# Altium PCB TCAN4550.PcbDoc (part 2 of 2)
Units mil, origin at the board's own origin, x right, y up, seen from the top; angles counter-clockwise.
Board outline 2000 x 1600 mil, 2 copper layers (Top Layer, Bottom Layer), stack 62 mil thick; 83 components, 51 nets, 217 pads, 26 vias.
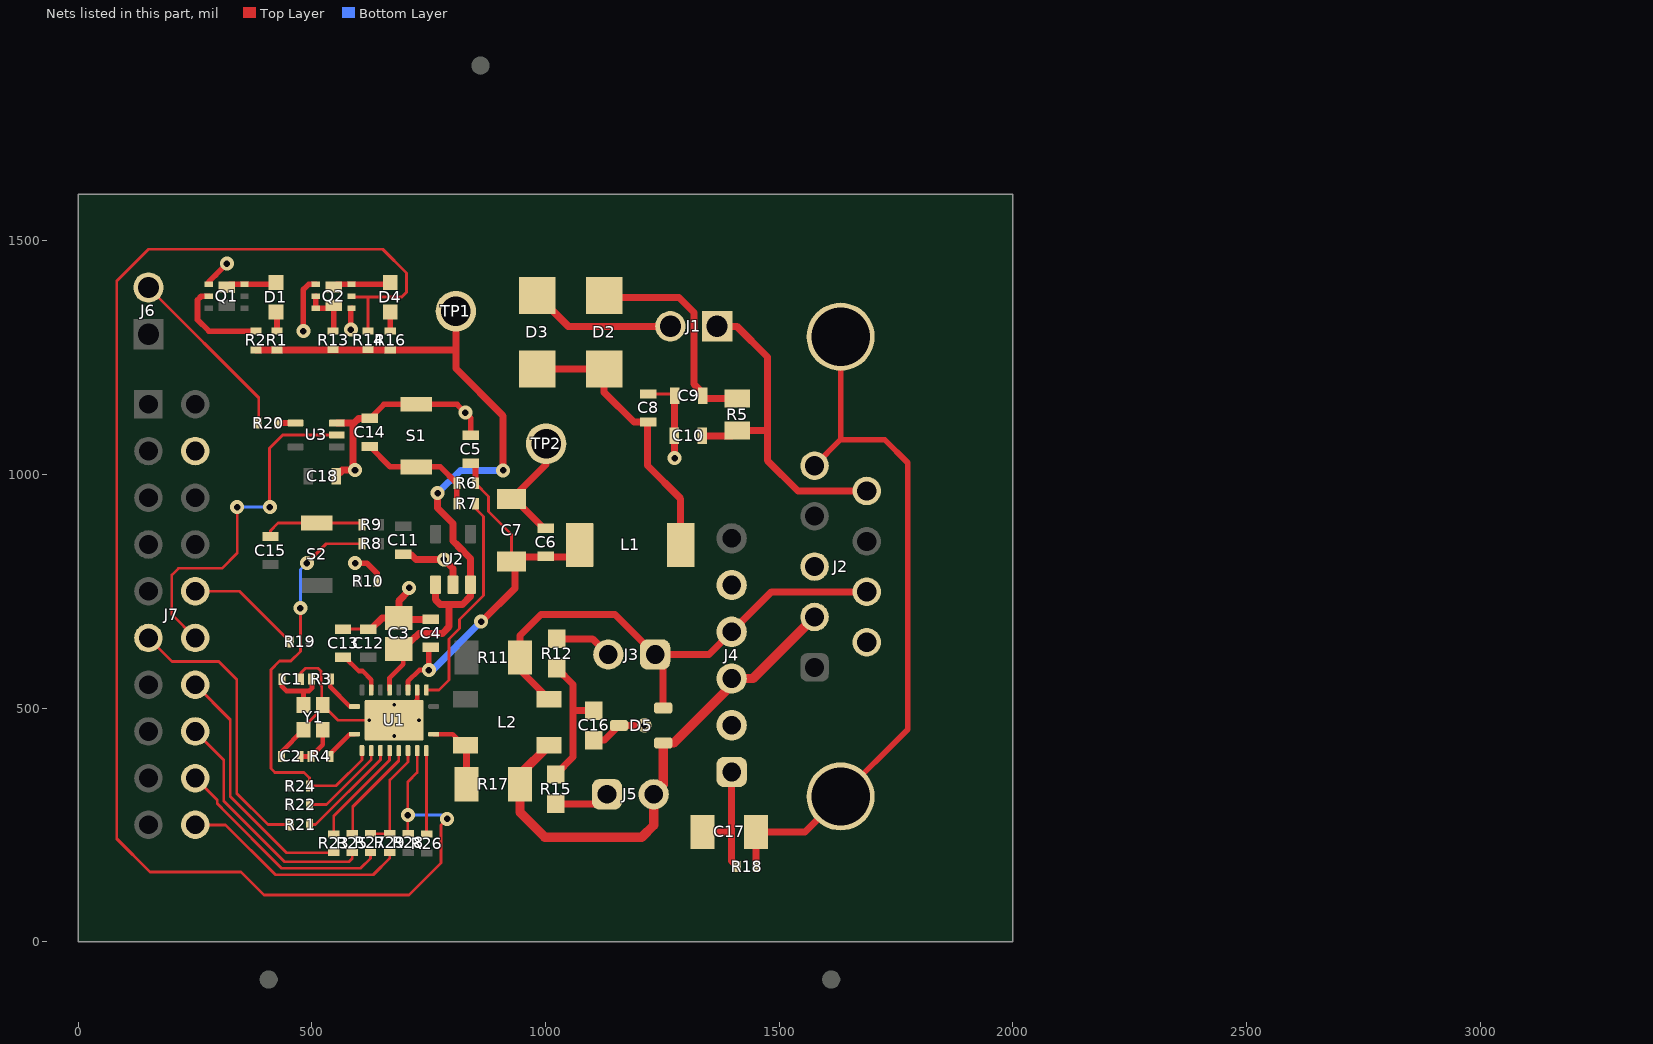
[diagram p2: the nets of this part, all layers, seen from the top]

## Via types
v1: diameter 30, hole 14, Top Layer to Bottom Layer, 22 vias
v2: diameter 19.68, hole 7.87, Top Layer to Bottom Layer, 4 vias

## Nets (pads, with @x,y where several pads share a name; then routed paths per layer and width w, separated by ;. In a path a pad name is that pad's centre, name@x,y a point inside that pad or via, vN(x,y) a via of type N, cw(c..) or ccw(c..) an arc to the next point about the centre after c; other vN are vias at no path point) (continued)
CANH_BUS: D5.2 J2.7 J3.1 J4.4 L2.4 R11.2 | length 1132.2
  Top Layer w15: L2.4@1007.53,519.04 945.05,581.53 R11.2@945.05,607.75 945.05,654.93 990.44,700.33 1148.53,700.33 J3.1@1234.31,614.55 J3.1@1242.89,614.55 ; D5.2@1251.66,500 1251.66,605.77 J3.1@1242.89,614.55 ; J2.7@1687.35,748.81 1483.78,748.81 J4.4@1398.15,663.19 1349.51,614.55 J3.1@1242.89,614.55
CANL: L2.2 R17.1 U1.10 | length 162.4
  Top Layer w10: U1.10@760.49,444.24 800.8,444.24 811.82,433.22 815.8,433.22 L2.2@828.4,420.62
  Top Layer w15: L2.2@828.4,420.62 830.87,418.14 R17.1@830.87,336.88
CANL_BUS: D5.1 J2.2 J4.3 J5.2 L2.3 R17.2 | length 1116.9
  Top Layer w20: L2.3@1007.53,420.62 945.05,358.13 R17.2@945.05,336.88 945.05,276.73 998,223.78 1206.04,223.78 1231.27,249.01 J5.2@1231.27,315.3 1251.66,335.69 D5.1@1251.66,425.2 1274.27,425.2 1398.15,549.08 J4.3@1398.15,563.19 1443.85,563.19 J2.2@1575.54,694.88
CRYSTAL1: C1.1 R3.2 Y1.1 | length 136.7
  Top Layer w10: C1.1@435.89,561.49 435.89,545.46 444.74,536.61 480,536.61 481.66,534.95 ; Y1.1@481.66,506.58 481.66,534.95 ; R3.2@499.38,561.86 500,561.24 500,542.28 494.34,536.61 481.66,536.61 481.66,534.95
CRYSTAL3: C2.1 R4.2 Y1.3 | length 91.2
  Top Layer w10: C2.1@474.24,396.43 R4.2@498.14,396.43 523,421.29 Y1.3@523,453.43
DB9_VBAT: C10.1 J1.1 J2.9 R5.2 | length 740.6
  Top Layer w15: C10.1@1335.54,1082.57 1398.61,1082.57 R5.2@1410.15,1094.11 1475,1094.11 ; J1.1@1367,1317 1409.08,1317 1475,1251.08 1475,1094.11 ; J2.9@1687.35,964.56 1539.7,964.56 1474.93,1029.34 1475,1029.41 1475,1094.11
FLTR: C13.1 U1.18 | length 102.3
  Top Layer w10: C13.1@566.37,608.9 570.49,608.9 600.1,579.3 608.13,579.3 626.63,560.8 U1.18@626.63,538.73
GND: C1.2 C2.2 C3.2 C4.2 C5.2 C6.2 C7.2 C8.2 C9.2 C10.2 C11.2 C12.2 C13.2 C14.2 C16.1 C17.2 C18.2 D3.2 D5.3 J1.2 J2.3 J2.6 J4.1 J4.2 J4.5 J7.4 Q1.4 Q2.1 Q2.4 R10.1 R18.1 S1.1 TP2.1 U1.13 U1.21 U2.2 U3.3 Y1.2 Y1.4 | length 2909.4
  Top Layer w6: C1.2@475.89,561.49 475.89,575.05 485.95,585.11 513.16,585.11 519.38,578.89 519.38,548.08 521,546.45 521,508.58 Y1.4@523,506.58 ; Y1.2@481.66,453.43 481.66,458.97 523,500.31 Y1.4@523,506.58 ; C13.2@572.39,668.9 C12.2@620.73,668.9 626.16,668.9 C12.2@626.63,669.37 ; U1.21@675.85,473.77 v2(622.7,473.77) 555.82,473.77 Y1.4@523,506.58 ; C8.2@1220,1172.16 1270.71,1172.16 1275.54,1167.33 C9.2@1276.31,1168.1
  Top Layer w10: C2.2@434.24,396.43 434.24,400.95 434.95,401.66 434.95,406.73 Y1.2@481.66,453.43 ; U1.21@675.85,473.77 680.5,473.77 725.06,518.32 U1.13@725.06,538.73
  Top Layer w12: Q1.4@278.77,1406.85 278.77,1411.72 293.69,1426.65 ; 293.67,1426.67 v1(318,1451) ; v1@318,1446.08 v1(318,1451) ; v1@318,1456.72 v1(318,1451) ; v1(481.66,1306.7) 481.66,1395.66 492.85,1406.85 Q2.4@508,1406.85 ; v1(583.02,1310) 583.02,1353.92 Q2.1@584.77,1355.67 ; v1(592.08,810) 617.44,810 639,788.44 R10.1@639,771.44 ; C14.2@623.78,1119.86 653.86,1149.94 S1.1@722.89,1149.94 810.46,1149.94 v1(828.4,1132) 840,1120.4 C5.2@840,1084
  Top Layer w15: C18.2@551.66,996 564.66,1009 v1(592,1009) 588,1013 588,1108.05 589.95,1110 ; U3.3@553.33,1110 589.95,1110 ; C14.2@623.78,1119.86 623.64,1120 599.95,1120 589.95,1110 ; C12.2@626.63,669.37 650.26,693 C3.2@685.69,693 687.05,694.36 C3.2@695.5,694.36 ; C11.2@695.33,829 711.33,829 722.33,818 v1(782.14,818) 801.82,798.31 U2.2@801.82,763.87 ; v1@707.93,751.21 685.69,728.97 685.69,704.18 C3.2@695.5,694.36 ; C4.2@754.28,689.27 700.6,689.27 C3.2@695.5,694.36 ; D3.2@982.21,1383.15 1048.36,1317 J1.2@1267,1317 ; C6.2@997.48,883.42 933.54,947.36 C7.2@927,947.36 1001,1021.36 TP2.1@1001,1065.75 ; C16.1@1102.8,431.25 1125.82,431.25 D5.3@1157.17,462.6 1204.42,462.6 1205.01,463.19 v1(1211.31,463.19) ; C9.2@1275.54,1167.33 C10.2@1275.54,1082.57 1275.54,1035.32 v1(1275.86,1035) ; C17.2@1336.07,234.83 1398.15,234.83 ; J4.1@1398.15,363.19 1398.15,234.83 ; R18.1@1410.51,160.74 1398.15,173.1 1398.15,234.83
  other v1: 707.93,757.29
  other v2: 675.85,440.3 729,473.77 675.85,507.23
GPIO1: R22.1 U1.3 | length 191.5
  Top Layer w6: R22.1@494.34,293.7 531.14,293.7 626.63,389.19 U1.3@626.63,408.81
GPIO_RST: J7.10 R19.1 | length 248.5
  Top Layer w6: J7.10@250,750 345.13,750 R19.1@453.57,641.55
GPO2: R26.1 U1.9 | length 179.1
  Top Layer w6: U1.9@744.74,408.81 744.74,230.7 R26.1@745.44,230
MCU_RST: J6.2 R20.1 | length 388.1
  Top Layer w6: J6.2@150,1400 386,1164 R20.1@386,1110 R20.1@386,1109.68
nCS: R27.2 R29.2 U1.7 | length 235.3
  Top Layer w6: R27.2@625,231.17 R29.2@666.55,231.17 666.55,345.91 705.37,384.73 U1.7@705.37,408.81
nINT: Q2.2 R14.1 R28.1 U1.8 | length 3245.1
  Top Layer w6: Q2.2@584.77,1381.26 586.02,1380 620,1380 ; R14.1@620,1307 620,1380 ; R28.1@706.04,231.17 705,232.21 v1(705,271) 705,342.05 725.06,362.11 U1.8@725.06,408.81 ; v1(789,263) 776,250 776,168.47 707.53,100 397,100 348,149 153.19,149 82,220.19 82,1414 150,1482 651.36,1482 702,1431.36 702,1389.79 692.21,1380 620,1380
  Bottom Layer w6: v1(705,271) 778.13,271 786.13,263 v1(789,263)
NINT_LED_INV: Q2.5 Q2.6 Q2.7 R13.1 | length 124.5
  Top Layer w12: Q2.5@508,1381.26 Q2.6@508,1355.67 540,1355.67 Q2.7@546.38,1362.04 546.38,1306.1 R13.1@545,1304.72
NINT_LEDA: D4.2 R16.1 | length 41.1
  Top Layer w12: R16.1@667.44,1306.7 D4.2@667.44,1347.78
NINT_LEDC: D4.1 Q2.3 Q2.8 | length 125.3
  Top Layer w12: Q2.8@546.38,1400.47 552.76,1406.85 Q2.3@584.77,1406.85 663.52,1406.85 D4.1@667.44,1410.77
nWRKQ: R8.1 R24.1 U1.2 | length 883.8
  Top Layer w6: v1(475.24,713.61) 475.24,658.09 475.2,658.06 475.2,621.2 454.55,600.55 430.55,600.55 412,582 412,370.44 420.44,362 483,362 494.34,350.66 R24.1@494.34,333.71 ; v1(488.83,810) 530.4,851.58 R8.1@606.63,851.58 ; R24.1@494.34,333.14 R24.1@494.34,333.71 ; U1.2@606.95,408.81 606.95,389.13 551.54,333.71 R24.1@494.34,333.71
  Bottom Layer w6: v1(475.24,713.61) 475.24,796.41 v1(488.83,810)
OSC1: R4.1 U1.1 | length 75.6
  Top Layer w10: R4.1@538.14,396.43 538.14,401.19 581.19,444.24 U1.1@591.2,444.24
OSC2: R3.1 U1.20 | length 85.9
  Top Layer w10: R3.1@539.38,561.86 539.38,545.16 581.24,503.29 U1.20@591.2,503.29
RST: J7.12 U3.2 | length 766
  Top Layer w6: J7.12@250,650 200,700 200,784.73 214.27,799 307,799 340,832 v1(340,930) ; v1(409.84,930) 409,930.84 409,1056.1 437.31,1084.41 U3.2@553.33,1084.41 U3.2@553.92,1084.41
  Bottom Layer w6: v1(340,930) v1(409.84,930)
RST_INV: R20.2 U3.4 | length 38.7
  Top Layer w12: R20.2@426,1110 U3.4@464.75,1110
RST_SW: C15.2 R9.1 S2.1 | length 216.1
  Top Layer w6: C15.2@411.13,867.12 411.13,879.5 427.56,895.93 S2.1@510,895.93 603.18,895.93 R9.1@606.63,892.48
SCLK: R21.1 U1.4 | length 229
  Top Layer w6: R21.1@494.34,250.57 507.64,250.57 646.32,389.26 U1.4@646.32,408.81
SDI: R23.2 U1.5 | length 227.9
  Top Layer w6: R23.2@546.38,230.41 546.38,268.53 666,388.15 U1.5@666,408.81
SDO: R25.2 U1.6 | length 218.9
  Top Layer w6: R25.2@586.17,231.16 587.26,232.25 587.26,288.77 685.69,387.2 U1.6@685.69,408.81
SHIELD_GND: C17.1 J2.5 J2.10 J2.11 R18.2 | length 1523.9
  Top Layer w12: J2.5@1575.54,1018.5 1631.45,1074.4 ; J2.11@1631.45,310.82 1775,454.38 1775,1025 1725.6,1074.4 1631.45,1074.4 ; J2.10@1631.45,1294.68 1631.45,1074.4
  Top Layer w15: R18.2@1450.51,160.74 1450.51,234.55 C17.1@1450.24,234.83 1555.45,234.83 J2.11@1631.45,310.82
SPI_CLK: J7.11 R21.2 | length 610.9
  Top Layer w6: J7.11@150,650 200.46,599.54 300.51,599.54 339,561.05 339,317.3 405.73,250.57 R21.2@452.69,250.57
SPI_CS_0: J7.18 R27.1 | length 481.4
  Top Layer w6: J7.18@250,350 297.13,302.87 297.13,295.41 305.99,286.54 305.99,285.76 434.59,157.16 604.06,157.16 625,178.1 R27.1@625,191.17
SPI_CS_1: J7.20 R29.1 | length 487.8
  Top Layer w6: J7.20@250,250 315.03,250 421.74,143.29 631.06,143.29 666.55,178.78 R29.1@666.55,191.17
SPI_MISO: J7.16 R25.1 | length 519.3
  Top Layer w6: J7.16@250,450 311,389 311,301.15 441.12,171.04 579.39,171.04 586.17,177.82 R25.1@586.17,191.16
SPI_MOSI: J7.14 R23.1 | length 541.7
  Top Layer w6: J7.14@250,550 325,475 325,310.49 328.25,307.23 ; 328.25,307.2 370.08,265.38 445.08,190.41 R23.1@546.38,190.41
SPLIT_TERM: C16.2 R12.1 R15.2 | length 301.1
  Top Layer w15: R15.2@1021.72,357.85 1058.86,394.99 1058.86,494.24 ; R12.1@1023.79,585.11 1058.9,550 1058.86,549.96 1058.86,494.24 ; C16.2@1102.8,494.24 1058.86,494.24
TERMH: J3.2 R12.2 | length 124.4
  Top Layer w15: R12.2@1023.79,648.1 1100.76,648.1 J3.2@1134.31,614.55
TERML: J5.1 R15.1 | length 118
  Top Layer w15: R15.1@1021.72,294.86 1110.83,294.86 J5.1@1131.27,315.3
VBAT: C8.1 D2.1 D3.1 L1.2 | length 607.5
  Top Layer w15: D3.1@982.21,1225.67 D2.1@1125.44,1225.67 1125.44,1175.63 1188.9,1112.16 C8.1@1220,1112.16 1218.07,1110.24 1218.07,1018.97 1289.17,947.87 L1.2@1289.17,849
VBAT_EXT_R: C9.1 D2.2 R5.1 | length 472.2
  Top Layer w15: D2.2@1125.44,1383.15 1125.44,1378.98 1285.07,1378.98 1317.43,1346.62 1317.43,1193.01 1336.31,1174.12 C9.1@1336.31,1168.1 1342.2,1162.22 R5.1@1410.15,1162.22
VCCOUT: C3.1 R1.2 R2.2 R13.2 R14.2 R16.2 TP1.1 U1.16 U2.1 U2.3 | length 1590
  Top Layer w10: U1.16@666,538.73 666,564.38 695.5,593.88 C3.1@695.5,611.72 ; C3.1@695.5,626.45 C3.1@695.5,627.43
  Top Layer w15: R2.2@380,1266.7 R1.2@425,1266.7 620,1266.7 R16.2@667.44,1266.7 808,1266.7 ; C3.1@695.5,627.43 720.11,652.04 721.58,652.04 729.09,659.54 778.99,659.54 793.47,674.02 793.47,721.8 ; U2.1@764.42,763.87 764.42,731.8 774.42,721.8 793.47,721.8 ; v1(769,959.85) 769,928 801.81,895.19 801.81,857.69 812.04,847.46 812.04,847.26 839.22,820.07 U2.3@839.22,763.87 839.22,739.16 821.86,721.8 793.47,721.8 ; TP1.1@808,1349.3 808,1266.7 ; v1(909,1008.5) 909,1125.49 808,1226.49 808,1266.7
  Bottom Layer w15: v1(769,959.85) 817.66,1008.5 v1(909,1008.5)
VCCOUT_LED: Q1.5 R2.1 | length 204.4
  Top Layer w12: Q1.5@278.77,1381.26 262.98,1381.26 255,1373.28 255,1331 279.3,1306.7 R2.1@380,1306.7
VCCOUT_LEDA: D1.2 R1.1 | length 41.9
  Top Layer w12: D1.2@422.94,1347.78 425,1345.72 R1.1@425,1306.7
VCCOUT_LEDC: D1.1 Q1.3 Q1.8 | length 110.1
  Top Layer w12: Q1.8@317.15,1400.47 323.53,1406.85 Q1.3@355.54,1406.85 419.02,1406.85 D1.1@422.94,1410.77
VSUP: C4.1 C5.1 C6.1 C7.1 L1.1 R6.2 U1.14 | length 824.3
  Top Layer w6: R6.2@849.89,981 878,952.89 878,920.5 927,871.5 C7.1@927,813.5
  Top Layer w10: U1.14@705.37,538.73 705.37,557.3 729.37,581.29 v1(750,581.29)
  Top Layer w12: v1(750,581.29) 750,625.95 C4.1@753.32,629.27 ; C5.1@840,1024 849.89,1014.11 R6.2@849.89,981
  Top Layer w15: v1(862.07,685) 862.93,685 934,756.07 934,806.5 C7.1@927,813.5 ; C7.1@944.7,823.42 1047.06,823.42 L1.1@1072.64,849
  Bottom Layer w15: v1(750,581.29) 758.36,581.29 v1(862.07,685)
WAKE: R7.2 U1.12 | length 461.9
  Top Layer w6: U1.12@744.74,538.73 772.09,538.73 793.47,560.11 793.47,648.03 815.8,670.36 815.8,689.75 867,740.95 867,909.88 R7.2@850,926.88
WAKE_SW: C14.1 R6.1 R7.1 S1.2 | length 262.7
  Top Layer w12: C14.1@623.78,1059.86 667.56,1016.08 S1.2@722.89,1016.08 774.81,1016.08 R6.1@809.89,981 810,980.89 R7.1@810,937.08
pads on no net: FID1.1 FID2.1 FID3.1 J2.1 J2.4 J2.8 J4.6 J7.1 J7.2 J7.3 J7.5 J7.6 J7.7 J7.8 J7.9 LBL1.0 Q1.1 Q1.2 Q1.6 Q1.7 U1.15 U2.4 U3.1

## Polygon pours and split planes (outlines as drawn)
GND on Bottom Layer "BOTTOM_LAYER_GND_P000" (solid, remove dead copper, pour order 0): 1950,1500 1900,1550 100,1550 50,1500 50,150 150,50 1897.99,50 1950,102.01

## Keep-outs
Keep-Out Layer:
  text ".Layer_Name" at 577,-858.49 h60

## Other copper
Top Layer:
  text ".Layer_Name" at 577,-858.49 h60
Bottom Layer:
  text ".Layer_Name" at 577,-858.49 h60

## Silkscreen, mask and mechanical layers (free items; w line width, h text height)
Top Overlay:
  text "'.PRJ_Number'.PCB_Rev" at 3397.7,133.34 h108.27
  text ".Layer_Name" at 577,-858.49 h60
Bottom Overlay:
  text ".Layer_Name" at 577,-858.49 h60
Top Paste:
  text ".Layer_Name" at 577,-858.49 h60
Bottom Paste:
  text ".Layer_Name" at 577,-858.49 h60
Top Solder:
  text ".Layer_Name" at 577,-858.49 h60
  text ".Layer_Name" at 577,-858.49 h60
Bottom Solder:
  text ".Layer_Name" at 577,-858.49 h60
Drill Guide:
  text ".Layer_Name" at 577,-858.49 h60
M1 Board Outline:
  the board outline again, w10
  text ".Layer_Name" at 577,-858.49 h60
M2 Board Dimensions:
  rectangle: 0,-275 125,-150
  rectangle: 125,-400 500,-275
  lines w7: 0,-275 1000,-275 ; 125,-400 125,-150 ; 250,-400 250,-150 ; 500,-400 500,-150 ; 750,-400 750,-150 ; 0,-400 1000,-400 1000,-150 0,-150 0,-400
  text ".Layer_Name" at 577,-858.49 h60
M3 3D STEP Top:
  text ".Layer_Name" at 577,-858.49 h60
M4 3D STEP Bottom:
  text ".Layer_Name" at 577,-858.49 h60
M5 Assembly Top:
  lines w10: -292,-930.17 6308,-930.17 ; -292,-726.83 6310,-726.83 ; -292,-523.5 -292,-1133.5 3713,-1133.5 6310,-1133.5 6310,-523.5 -291.5,-523.5 -291.5,-1133.5 1284,-1133.5 ; 2173,-1133.5 2173,-523.5 ; 3440,-726.83 3440,-523.5 ; 4280,-726.83 4280,-523.5 ; 4902,-1140 4902,-937.17
  text "COMPONENTS MARKED 'DNP' SHOULD NOT BE POPULATED." at 1153.5,-318.5 h60
  text "ASSEMBLY VARIANT:" at 1153,-434 h60
  text ".VariantName" at 2189,-434 h60
  text "PCB VIEWED FROM TOP SIDE" at -228.5,-655.67 h60
  text "BOARD #:" at 2248,-655.67 h60
  text ".PRJ_Number" at 2793.5,-655.67 h60
  text "REV:" at 3638,-655.67 h60
  text ".PCB_Rev" at 3929.5,-655.67 h60
  text "SVN REV:" at 4476,-655.67 h60
  text ".VersionControl_RevNumber" at 4982,-655.67 h60
  text "TID #:" at 2248,-859 h60
  text ".TID" at 2793.5,-859 h60
  text "PLOT NAME =" at -228.5,-1064.34 h60
  text ".plot_File_Name" at 577,-1064.34 h60
  text "GENERATED    :" at 2250,-1064.34 h60
  text ".Print_Date" at 3119.5,-1064.34 h60
  text ".Print_Time" at 3848.5,-1064.34 h60
  text "TEXAS INSTRUMENTS" at 5113,-1064.34 h60
M6 Assembly Bottom:
  lines w10: -292.5,-727.33 6309.5,-727.33 ; -290.5,-930.67 6309.5,-930.67 ; 1115.5,-1140.5 1115.5,-937.67 ; 1737.5,-727.33 1737.5,-524 ; 2577.5,-727.33 2577.5,-524 ; 3844.5,-1134 3844.5,-524 ; 4733.5,-1134 6309,-1134 6309,-524 -292.5,-524 -292.5,-1134 2304.5,-1134 6309.5,-1134 6309.5,-524
  text "COMPONENTS MARKED 'DNP' SHOULD NOT BE POPULATED." at 6102,-318 h60
  text ".VariantName" at 5058,-434 h60
  text "ASSEMBLY VARIANT:" at 6097,-434 h60
  text ".VersionControl_RevNumber" at 1035.5,-656.17 h60
  text "SVN REV:" at 1541.5,-656.17 h60
  text ".PCB_Rev" at 2088,-656.17 h60
  text "REV:" at 2379.5,-656.17 h60
  text ".PRJ_Number" at 3224,-656.17 h60
  text "BOARD #:" at 3769.5,-656.17 h60
  text "PCB VIEWED FROM BOTTOM SIDE" at 6246,-656.17 h60
  text ".TID" at 3224,-859.5 h60
  text "TID #:" at 3769.5,-859.5 h60
  text "TEXAS INSTRUMENTS" at 904.5,-1064.84 h60
  text ".Print_Time" at 2169,-1064.84 h60
  text ".Print_Date" at 2898,-1064.84 h60
  text "GENERATED    :" at 3767.5,-1064.84 h60
  text ".plot_File_Name" at 5440.5,-1064.84 h60
  text "PLOT NAME =" at 6246,-1064.84 h60
M9 Title Sheet:
  drawing of 57 lines, arcs and shapes, not listed
  text "1" at 739.84,8036.5 h70
  text "2" at 3235.5,8036.5 h70
  text "3" at 5724.84,8036.5 h70
  text "4" at 8231.51,8036.5 h70
  text "5" at 10730.5,8036.5 h70
  text "6" at 13235.5,8036.5 h70
  text "A" at -416.5,6893.5 h70
  text "A" at 14383.5,6893.5 h70
  text "B" at -416.5,4513.5 h70
  text "B" at 14383.5,4513.5 h70
  text "C" at -416.5,2138.5 h70
  text "C" at 14383.5,2138.5 h70
  text "PROJECT TITLE:" at 11343.5,277.5 h45
  text ".PRJ_Title" at 11393.5,144.17 h70
  text "DESIGNED FOR:" at 11343.5,-23.5 h45
  text ".PRJ_Customer" at 11393.5,-163.5 h70
  text "D" at -416.5,-231.5 h70
  text "D" at 14383.5,-231.5 h70
  text "FILE NAME:" at 11343.5,-323.5 h45
  text ".PCB_File_Name_No_Path" at 11393.5,-443.5 h70
  text "Texas Instruments (TI) and/or its licensors do not warrant the accuracy or completeness of this specification" at 6374,-605.34 h45
  text "ENGINEER:" at 11343.5,-613.5 h45
  text "LAYOUT BY:" at 12848.5,-613.5 h45
  text "or any information contained therein. TI and/or its licensors do not warrant that this design will meet" at 6329.01,-718 h45
  text ".PRJ_Engineer" at 11393.5,-768.49 h70
  text ".PCB_Layout" at 12899,-768.49 h70
  text "the specifications, will be suitable for your application or fit for any particular purpose, or will operate in" at 6329.01,-830.67 h45
  text ".Layer_Name" at 577,-858.49 h60
  text "ALTIUM DESIGNER VERSION:" at 12848.5,-923.5 h45
  text "an implementation. TI and/or its licensors do not warrant that the design is production worthy. You should" at 6329.01,-943.33 h45
  text "completely validate and test your design implementation to confirm the system functionality for your application." at 6374,-1056 h45
  text ".print_Scale" at 11393.5,-1056.83 h70
  text ".Application_BuildNumber" at 12899,-1056.83 h70
  text "1" at 739.84,-1263.5 h70
  text "2" at 3235.5,-1263.5 h70
  text "3" at 5724.84,-1263.5 h70
  text "4" at 8231.51,-1263.5 h70
  text "5" at 10730.5,-1263.5 h70
  text "6" at 13235.5,-1263.5 h70
M10 Fab Notes:
  drawing of 189 lines, arcs and shapes, not listed
  text "DESIGN INFORMATION" at 12382.02,6356.17 h60
  text "MIN. TRACK WIDTH:" at 11737.46,6224.05 h60
  text "8" at 12833.7,6224.05 h60
  text "MIL" at 12988.46,6224.05 h60
  text "MIN. CLEARANCE:" at 11737.46,6099.92 h60
  text "0.2" at 12773.7,6099.93 h60
  text "mm" at 12988.46,6099.92 h60
  text "MIN. VIA PAD SIZE:" at 11737.46,5975.8 h60
  text "24" at 12803.71,5975.8 h60
  text "MIL" at 12988.46,5975.8 h60
  text "0.05mm (2MIL)" at 12432.46,5845.9 h60
  text "MINIMUM ANNULAR RING" at 11408.23,5837.67 h60
  text "EXTERNAL" at 13140.46,5837.67 h60
  text "PER" at 11608.23,5727.55 h60
  text "IPC-D-275 CLASS 2 LEVEL C" at 11828.23,5727.54 h60
  text "MIL, HOLES" at 13316.46,5627.07 h60
  text "+/-" at 12924,5618.48 h60
  text "+/-" at 13778,5618.48 h60
  text "REGISTRATION TOLERANCES:" at 11408.23,5617.42 h60
  text "METAL" at 12608,5617.42 h60
  text "5" at 13184.2,5617.42 h60
  text "3" at 14017.2,5617.42 h60
  text "MIL" at 14133.46,5617.42 h60
  text "HOLE SIZE TOLERANCE (UNLESS OTHERWISE SPECIFIED):" at 11408.23,5519.1 h60
  text "+/-" at 13778,5516.23 h60
  text "3" at 14017.2,5515.17 h60
  text "MIL" at 14133.46,5515.17 h60
  text "MATERIAL:" at 11333.46,5377.52 h60
  text "FR-4 High Tg" at 12319.9,5249 h60
  text "X" at 12175.46,5241.01 h60
  text "FR-408" at 11754.46,5236.49 h60
  text "OTHER" at 13242.46,5236.49 h60
  text "62 MIL (1.6mm) +/-10%" at 12074.56,5093.46 h60
  text "X" at 11954.46,5091.01 h60
  text "THICKNESS:" at 11408.23,5085.24 h60
  text "OTHER" at 13359.46,5085.24 h60
  text "TOLERANCE:" at 11408.23,4946.92 h60
  text "X" at 12256.46,4946.92 h60
  text "ANSI IPC-6012 TYPE 3 CLASS 2" at 12434.48,4946.92 h60
  text "OTHER +/-" at 12434.46,4802.73 h60
  text "BOW & TWIST:" at 11408.23,4657.54 h60
  text "X" at 12256.46,4657.54 h60
  text "ANSI IPC-6012 TYPE 3 CLASS 2" at 12434.48,4657.54 h60
  text "OTHER +/-" at 12434.46,4510.85 h60
  text "DRILLING:" at 11333.46,4380.23 h60
  text "NC_DRILL FILES" at 13094.46,4275.04 h60
  text "REFERENCE:" at 11408.23,4271.1 h60
  text "X" at 12065.46,4271.01 h60
  text "AS SHOWN" at 12243.46,4271.1 h60
  text "X" at 12966.46,4271.1 h60
  text "OTHER" at 13392.46,4128.85 h60
  text "PTH COPPER THICKNESS:" at 11407.91,4125.32 h60
  text "X" at 12547.14,4125.32 h60
  text "20-30 um" at 12675.14,4125.32 h60
  text "BOARD FINISH:" at 11333.46,3977.73 h60
  text "SILKSCREEN:" at 11488.68,3867.6 h60
  text "X" at 12446.46,3867.6 h60
  text "TOP" at 12563.46,3867.6 h60
  text "X" at 12956.46,3867.6 h60
  text "BOTTOM" at 13074.46,3867.6 h60
  text "SILKSCREEN COLOR:" at 11488.68,3712.41 h60
  text "X" at 12445.46,3712.41 h60
  text "WHITE" at 12563.46,3712.41 h60
  text "OTHER" at 13074.46,3712.41 h60
  text "X" at 12576.46,3568.96 h60
  text "GREEN" at 12694.46,3568.96 h60
  text "OTHER" at 13312.46,3568.96 h60
  text "SOLDER RESIST COLOR:" at 11488.68,3562.1 h60
  text "X" at 12576.46,3414.71 h60
  text "MATTE" at 12694.46,3414.71 h60
  text "SEMI-GLOSS" at 13312,3414.07 h60
  text "IMMERSION GOLD (ENIG)" at 12394.46,3241.94 h60
  text "ENEPIG" at 13732,3234.72 h60
  text "SURFACE FINISH:" at 11333.46,3233.72 h60
  text "X" at 12216.46,3233.72 h60
  text "IMM. TIN/SILVER OR EQUIV" at 11663,3096.4 h60
  text "OTHER" at 13094.46,3092.47 h60
  text "ARRAY/PANEL:" at 11333.46,2937.09 h60
  text "CUT AND TRIM PER M1 BOARD OUTLINE" at 12394.46,2928.87 h60
  text "N.C. ROUTE" at 12394.46,2792.9 h60
  text "X" at 13082.46,2792.9 h60
  text "V. SCORE" at 13260.46,2792.9 h60
  text "CERTIFICATION:" at 11333.46,2663.77 h60
  text "MATERIALS AND WORKMANSHIP FOR ALL PCBS" at 12058.46,2663.77 h60
  text "TO MEET OR EXCEED THE REQUIREMENTS OF:" at 12058.46,2569.71 h60
  text "X" at 11695.97,2441.08 h60
  text "ANSI IPC-A-600F CLASS ->" at 11823.96,2441.08 h60
  text "X" at 13471.97,2441.08 h60
  text "2" at 13581.96,2441.08 h60
  text "1" at 13266.96,2439.58 h60
  text "3" at 13935.96,2439.58 h60
  text "X" at 12507.97,2293.39 h60
  text "RoHS" at 12635.96,2293.39 h60
  text "OTHER" at 13280.36,2293.39 h60
  text "PER ORDER" at 13677.42,2293.39 h60
  text "ALL BOARDS MUST MEET OR EXCEED UL94-V0 REQUIREMENTS." at 11361,2139.57 h60
  text "PCB MUST BEAR THE UL94V-0 UL REGISTERED MATERIAL ID NUMBER" at 11361,2023.5 h60
  text "ADDITIONAL REQUIREMENTS:" at 11333.46,1854.08 h60
  text "MICROSECTION:" at 11408.23,1746.95 h60
  text "YES" at 12313.96,1746.95 h60
  text "REQUIRED" at 13175.46,1602.62 h60
  text "BARE BOARD ELEC. TEST:" at 11408.23,1599.76 h60
  text "NONE" at 12713.96,1599.76 h60
  text "X" at 13057.46,1599.76 h60
  text "PER ORDER" at 13767.46,1599.76 h60
  text "XX MIL VIAS REQUIRE NON-CONDUCTIVE FILL AND PLANARIZE" at 11576.38,1394.82 h59
  text "XX MIL VIAS REQUIRE CONDUCTIVE FILL AND PLANARIZE" at 11584.38,1290.84 h60
  text "OUTER XX MIL TRACES REQUIRE 50 OHM SINGLE-ENDED IMPEDANCE" at 11583.39,1127.46 h58
  text "LAYER 2 & 3 (INNER LAYERS) XX MIL WIDE, XX MIL SPACE / TRACES REQUIRE 100 OHM DIFFERENTIAL IMPEDANCE" at 11575.39,891.74 h60
  text ".Layer_Name" at 577,-858.49 h60
M11 Gerber Information:
  lines w10: -292,-930.17 6308,-930.17 ; -292,-726.83 6310,-726.83 ; -292,-523.5 -292,-1133.5 3713,-1133.5 6310,-1133.5 6310,-523.5 -291.5,-523.5 -291.5,-1133.5 1284,-1133.5 ; 2173,-1133.5 2173,-523.5 ; 3440,-726.83 3440,-523.5 ; 4280,-726.83 4280,-523.5 ; 4902,-1140 4902,-937.17
  text "ALL ARTWORK VIEWED FROM TOP SIDE" at -228.5,-655.67 h60
  text "BOARD #:" at 2248,-655.67 h60
  text ".PRJ_Number" at 2793.5,-655.67 h60
  text "REV:" at 3638,-655.67 h60
  text ".PCB_Rev" at 3929.5,-655.67 h60
  text "SVN REV:" at 4476,-655.67 h60
  text ".VersionControl_RevNumber" at 4982,-655.67 h60
  text "LAYER NAME =" at -228.5,-858.49 h60
  text "TID #:" at 2248,-859 h60
  text ".TID" at 2793.5,-859 h60
  text "PLOT NAME =" at -228.5,-1064.34 h60
  text ".plot_File_Name" at 577,-1064.34 h60
  text "GENERATED    :" at 2250,-1064.34 h60
  text ".Print_Date" at 3119.5,-1064.34 h60
  text ".Print_Time" at 3848.5,-1064.34 h60
  text "TEXAS INSTRUMENTS" at 5113,-1064.34 h60
M12 Stackup:
  drawing of 191 lines, arcs and shapes, not listed
  text "Layer" at 9811.59,7807.44 h60
  text "Name" at 10221.51,7807.44 h60
  text "Material" at 11151.25,7807.44 h60
  text "Thickness" at 12011.02,7807.44 h60
  text "Constant" at 12660.85,7807.44 h60
  text "Board Layer Stack" at 13230.71,7807.44 h60
  text "1" at 9811.59,7687.44 h60
  text "Top Overlay" at 10221.51,7687.44 h60
  text "2" at 9811.59,7567.44 h60
  text "Top Solder" at 10221.51,7567.44 h60
  text "Solder Resist" at 11151.25,7567.44 h60
  text "0.40mil" at 12011.02,7567.44 h60
  text "3.5" at 12660.85,7567.44 h60
  text "3" at 9811.59,7447.44 h60
  text "Top Layer" at 10221.51,7447.44 h60
  text "Copper" at 11151.25,7447.44 h60
  text "1.40mil" at 12011.02,7447.44 h60
  text "4" at 9811.59,7327.44 h60
  text "Dielectric1" at 10221.51,7327.44 h60
  text "FR-4" at 11151.25,7327.44 h60
  text "59.20mil" at 12011.02,7327.44 h60
  text "4.8" at 12660.85,7327.44 h60
  text "5" at 9811.59,7207.44 h60
  text "Bottom Layer" at 10221.51,7207.44 h60
  text "Copper" at 11151.25,7207.44 h60
  text "1.40mil" at 12011.02,7207.44 h60
  text "6" at 9811.59,7087.44 h60
  text "Bottom Solder" at 10221.51,7087.44 h60
  text "Solder Resist" at 11151.25,7087.44 h60
  text "0.40mil" at 12011.02,7087.44 h60
  text "3.5" at 12660.85,7087.44 h60
  text "7" at 9811.59,6967.44 h60
  text "Bottom Overlay" at 10221.51,6967.44 h60
  text ".Layer_Name" at 577,-858.49 h60
M13 Component Bodies Top:
  text ".Layer_Name" at 577,-858.49 h60
M14 Component Bodies Bottom:
  text ".Layer_Name" at 577,-858.49 h60
M15 Courtyards Top:
  text ".Layer_Name" at 577,-858.49 h60
M16 Courtyards Bottom:
  text ".Layer_Name" at 577,-858.49 h60
Drill Drawing:
  circle w10: c5363.72,2941.32 r27.63
  lines w10: 5336.09,2416.42 5363.72,2430.23 5391.34,2416.42 5377.53,2444.04 5391.34,2471.67 5363.72,2457.86 5336.09,2471.67 5349.9,2444.04 5336.09,2416.42 ; 5336.09,2595.99 5391.34,2595.99 5363.72,2540.74 5336.09,2595.99 ; 5336.09,2665.06 5391.34,2665.06 5391.34,2720.31 5336.09,2720.31 5336.09,2665.06 ; 5336.09,2803.19 5349.9,2803.19 5363.72,2789.38 5377.53,2803.19 5391.34,2803.19 5377.53,2817 5391.34,2830.82 5377.53,2830.82 5363.72,2844.63 5349.9,2830.82 5336.09,2830.82 5349.9,2817 5336.09,2803.19 ; 5336.09,3051.83 5349.9,3051.83 5349.9,3038.02 5377.53,3038.02 5377.53,3051.83 5391.34,3051.83 5391.34,3079.46 5377.53,3079.46 5377.53,3093.27 5349.9,3093.27 5349.9,3079.46 5336.09,3079.46 5336.09,3051.83 ; 5336.09,3162.34 5391.34,3162.34 5391.34,3217.59 5336.09,3217.59 5336.09,3162.34 ; 5336.09,3314.28 5363.72,3286.66 5391.34,3314.28 5363.72,3341.91 5336.09,3314.28 ; 5347.14,2676.11 5380.29,2676.11 5380.29,2709.26 5347.14,2709.26 5347.14,2676.11
  lines w12: 5286,2379.12 8517.49,2379.12 ; 5286,3373.68 8517.49,3373.68 ; 5623.86,2254.8 5623.86,3498 ; 5955.86,2254.8 5955.86,3498 ; 6592.43,2254.8 6592.43,3498 ; 6851.57,2254.8 6851.57,3498 ; 7226.72,2254.8 7226.72,3498 ; 7951.05,2254.8 7951.05,3498 ; 5286,2254.8 8517.49,2254.8 8517.49,3498 5286,3498 5286,2254.8
  text "Symbol" at 5360.59,3410.98 h72
  text "Quantity" at 5661.16,3410.98 h72
  text "Finished Hole Size" at 5993.16,3410.98 h72
  text "Plated" at 6629.72,3410.98 h72
  text "Hole Type" at 6888.86,3410.98 h72
  text "Drill Layer Pair" at 7264.02,3410.98 h72
  text "Hole Tolerance" at 7988.35,3410.98 h72
  text "4" at 5661.16,3286.66 h60
  text "7.87mil (0.200mm)" at 5993.16,3286.66 h60
  text "PTH" at 6629.72,3286.66 h60
  text "Round" at 6888.86,3286.66 h60
  text "Top Layer - Bottom Layer" at 7264.02,3286.66 h60
  text "22" at 5661.16,3162.34 h60
  text "14.00mil (0.356mm)" at 5993.16,3162.34 h60
  text "PTH" at 6629.72,3162.34 h60
  text "Round" at 6888.86,3162.34 h60
  text "Top Layer - Bottom Layer" at 7264.02,3162.34 h60
  text "10" at 5661.16,3038.02 h60
  text "40.00mil (1.016mm)" at 5993.16,3038.02 h60
  text "PTH" at 6629.72,3038.02 h60
  text "Round" at 6888.86,3038.02 h60
  text "Top Layer - Bottom Layer" at 7264.02,3038.02 h60
  text "20" at 5661.16,2913.7 h60
  text "40.16mil (1.020mm)" at 5993.16,2913.7 h60
  text "PTH" at 6629.72,2913.7 h60
  text "Round" at 6888.86,2913.7 h60
  text "Top Layer - Bottom Layer" at 7264.02,2913.7 h60
  text "9" at 5661.16,2789.38 h60
  text "40.95mil (1.040mm)" at 5993.16,2789.38 h60
  text "PTH" at 6629.72,2789.38 h60
  text "Round" at 6888.86,2789.38 h60
  text "Top Layer - Bottom Layer" at 7264.02,2789.38 h60
  text "4" at 5661.16,2665.06 h60
  text "45.28mil (1.150mm)" at 5993.16,2665.06 h60
  text "PTH" at 6629.72,2665.06 h60
  text "Round" at 6888.86,2665.06 h60
  text "Top Layer - Bottom Layer" at 7264.02,2665.06 h60
  text "2" at 5661.16,2540.74 h60
  text "63.00mil (1.600mm)" at 5993.16,2540.74 h60
  text "PTH" at 6629.72,2540.74 h60
  text "Round" at 6888.86,2540.74 h60
  text "Top Layer - Bottom Layer" at 7264.02,2540.74 h60
  text "2" at 5661.16,2416.42 h60
  text "124.80mil (3.170mm)" at 5993.16,2416.42 h60
  text "PTH" at 6629.72,2416.42 h60
  text "Round" at 6888.86,2416.42 h60
  text "Top Layer - Bottom Layer" at 7264.02,2416.42 h60
  text "73 Total" at 5661.16,2292.1 h60
  text ".Layer_Name" at 577,-858.49 h60
M17 Embedded Cavity:
  text ".Layer_Name" at 577,-858.49 h60
M18 Embedded Assembly:
  text ".Layer_Name" at 577,-858.49 h60
M19 Embedded Keepout:
  text ".Layer_Name" at 577,-858.49 h60

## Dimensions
0,-400 to 1000,-400 on M2 Board Dimensions
0,0 to 2000,0 on M2 Board Dimensions
0,0 to 0,1600 on M2 Board Dimensions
